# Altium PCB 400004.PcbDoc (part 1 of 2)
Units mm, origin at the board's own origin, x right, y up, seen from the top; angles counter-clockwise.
Board outline 80 x 40 mm, 4 copper layers (Top Layer, Mid-Layer 1, Mid-Layer 2, Bottom Layer), stack 1.582 mm thick; 116 components, 104 nets, 453 pads, 327 vias.
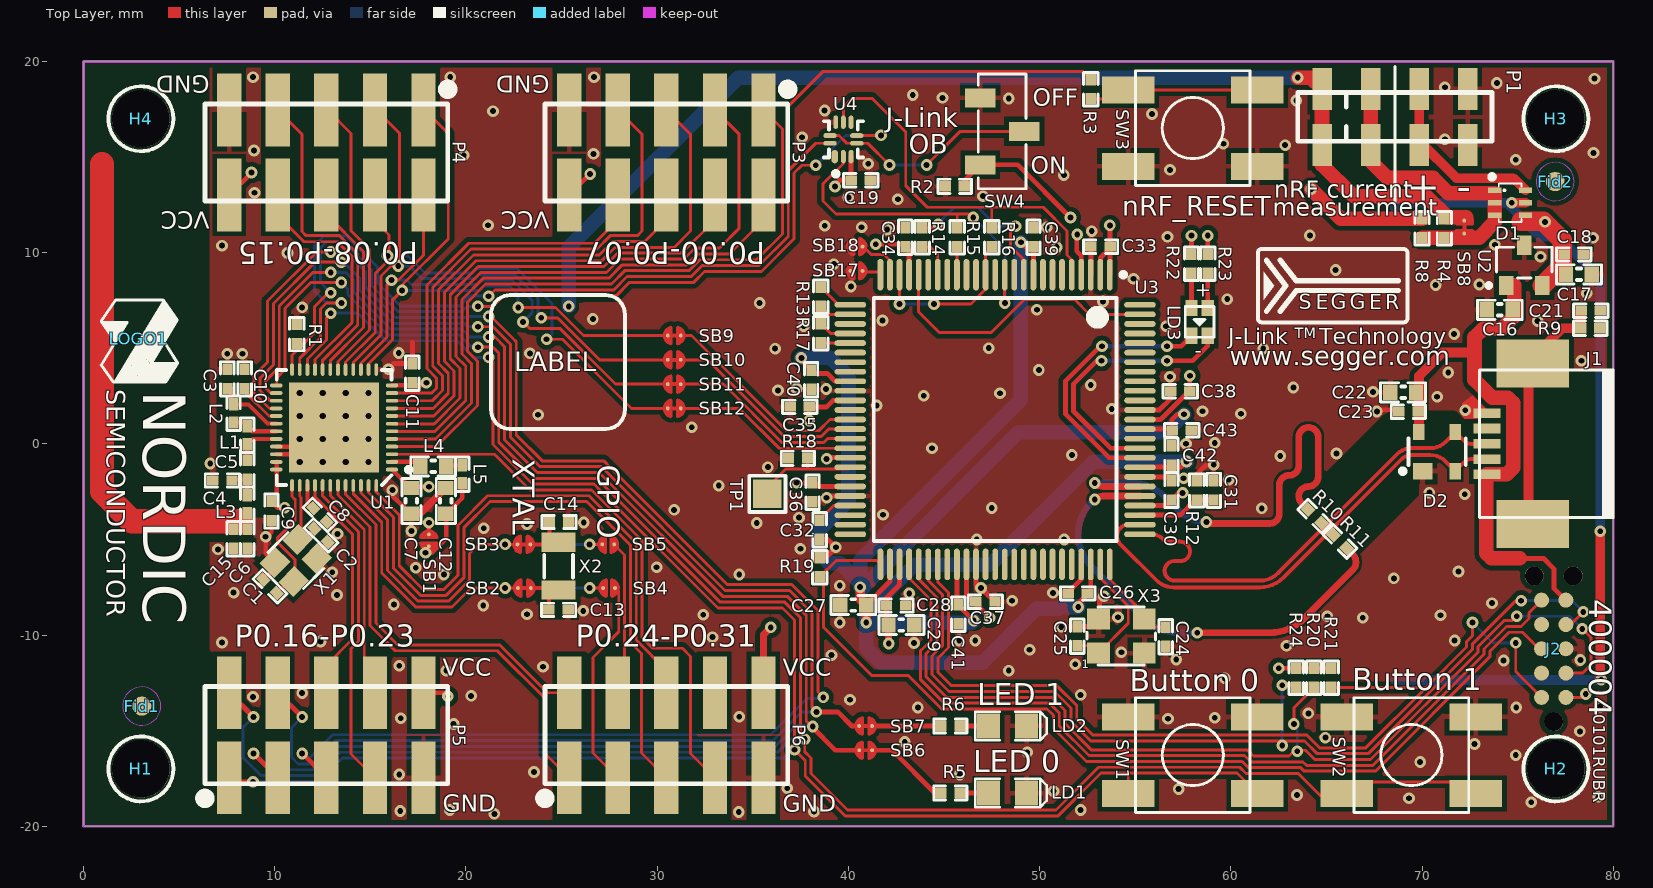
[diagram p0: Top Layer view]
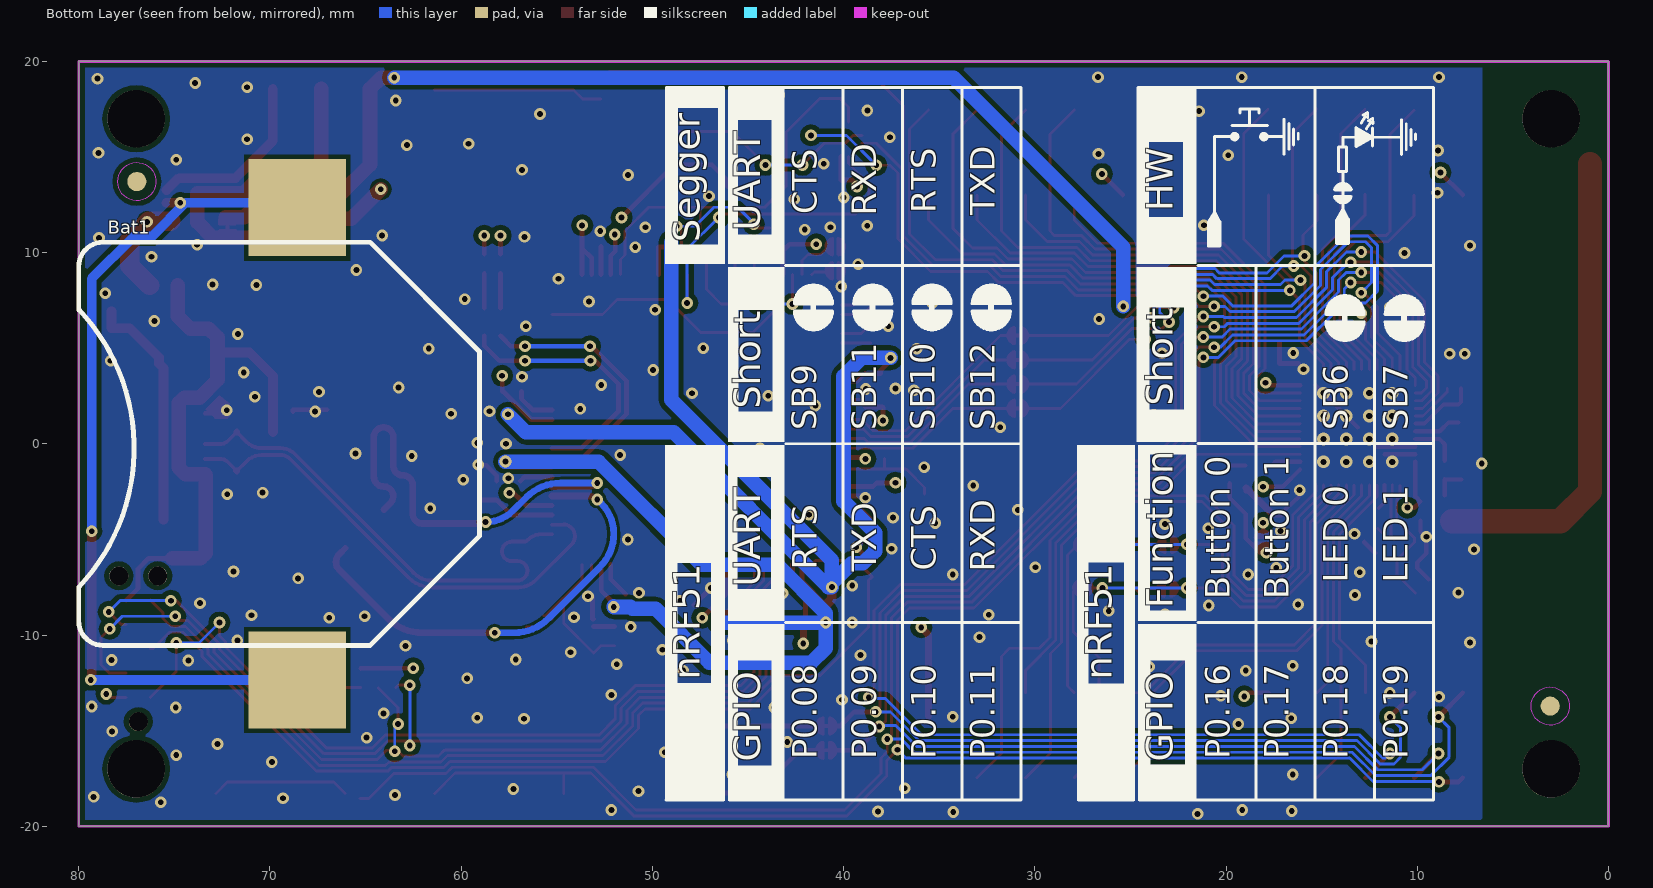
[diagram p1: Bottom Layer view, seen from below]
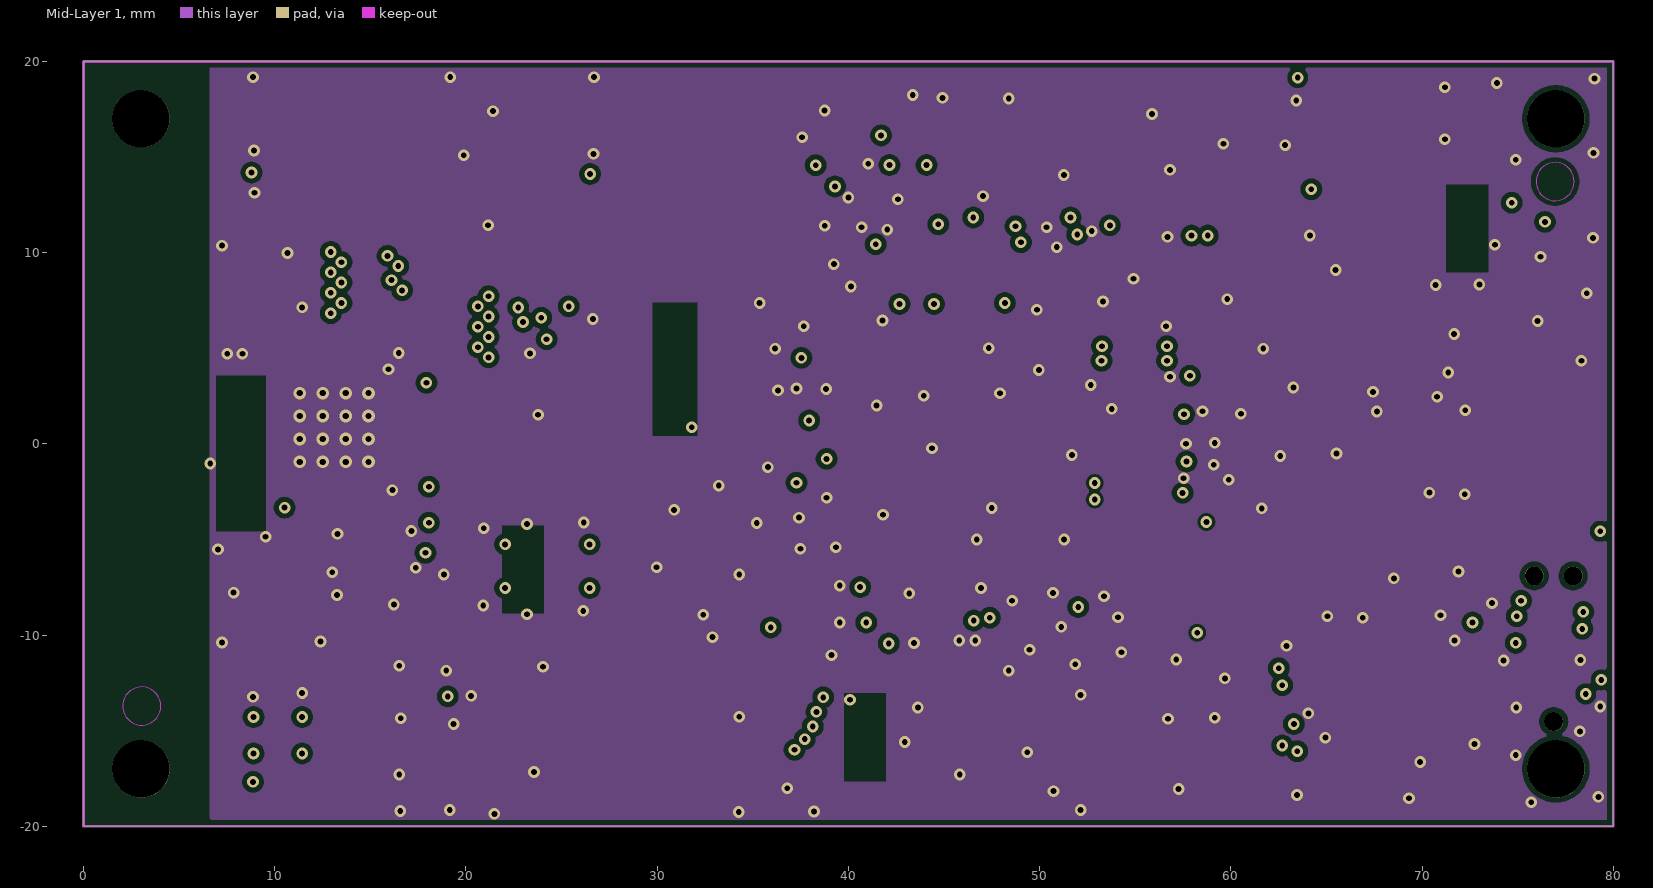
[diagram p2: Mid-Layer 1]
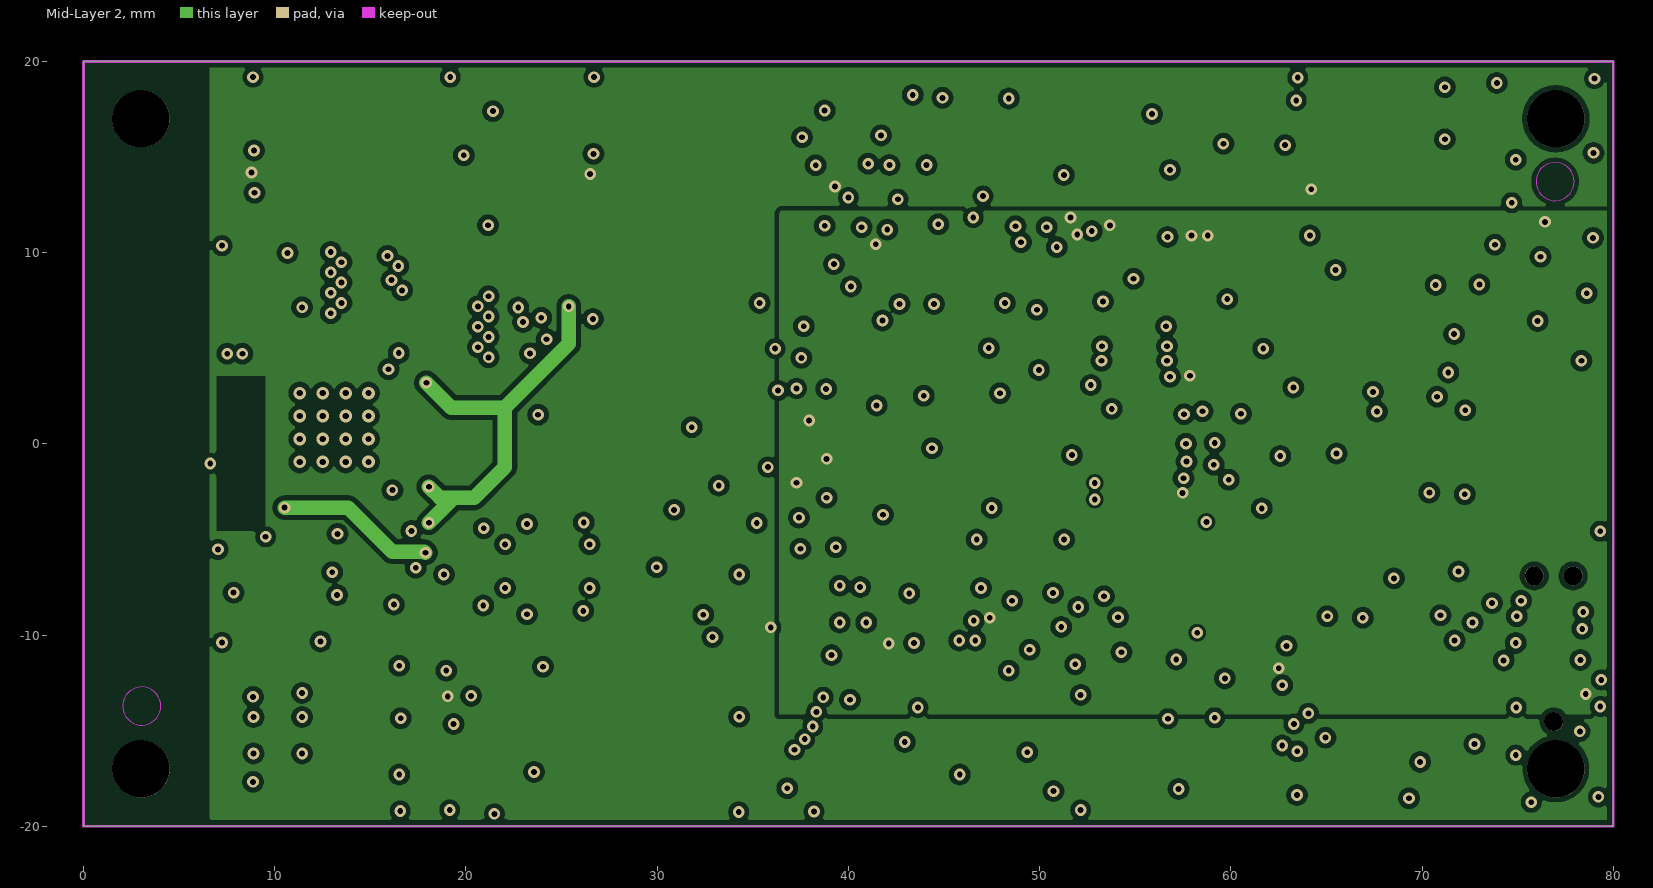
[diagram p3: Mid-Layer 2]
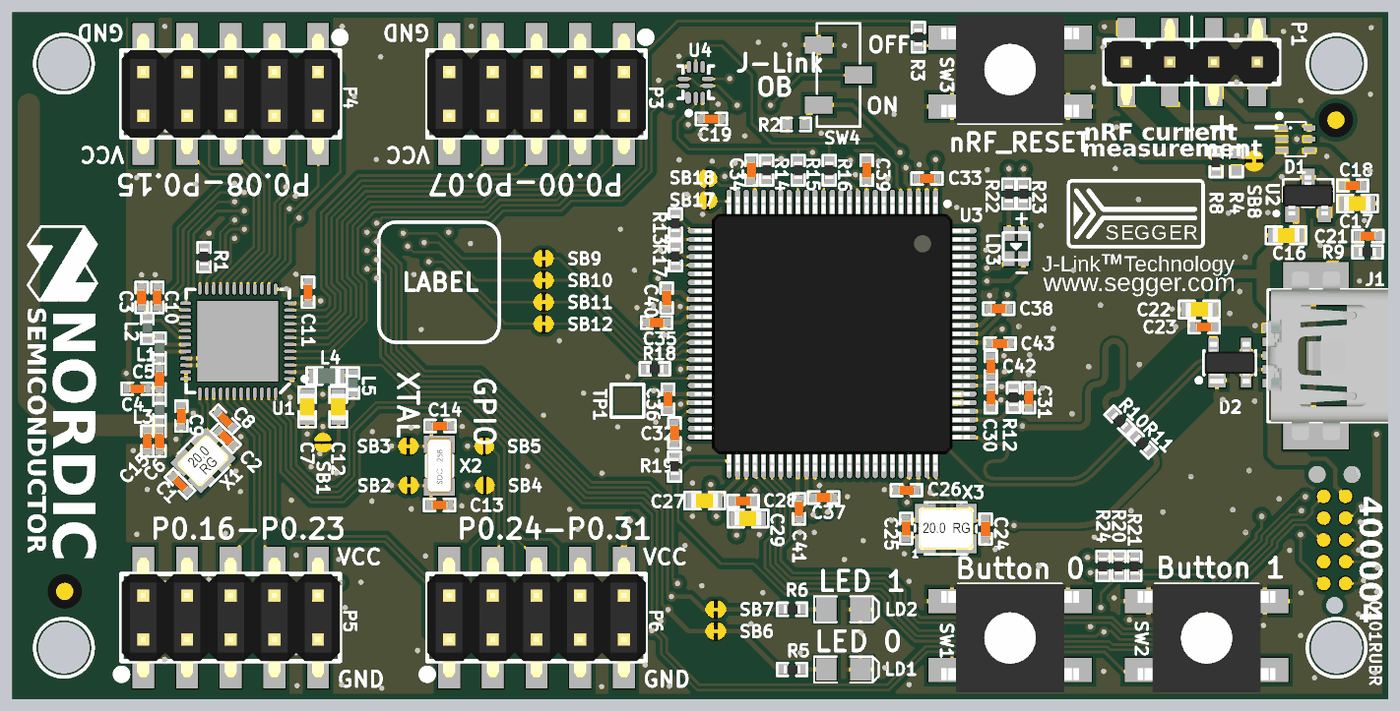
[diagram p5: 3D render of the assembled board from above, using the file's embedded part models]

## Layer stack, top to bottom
Top Layer: signal copper 0.0356
Dielectric: prepreg 0.18, FR-4, Dk 4.4
Mid-Layer 1: signal copper 0.0356
Dielectric: core 1.08, FR-4, Dk 4.4
Mid-Layer 2: signal copper 0.0356
Dielectric: prepreg 0.18, FR-4, Dk 4.4
Bottom Layer: signal copper 0.0356

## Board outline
0,-20 80,-20 80,20 0,20

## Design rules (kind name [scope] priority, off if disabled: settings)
Clearance USB_Poly_Clearance [(InNamedPolygon('Top_Layer-GND')) vs (OnLayer('Mechanical 3'))] p1: gap=0.254
Clearance USB_Clearance [(InDifferentialPairClass('All Differential Pairs'))] p2: gap=0.152
Clearance ANT_Clerance [InNet('ANT')] p3: gap=0.127
Clearance Polygon_Clearance [(InNamedPolygon('Top_Layer-GND')) or (InNamedPolygon('Bottom_Layer-GND')) or (InNamedPolygon('Mid_Layer_1-GND')) or (InNamedPolygon('Mid_Layer_2-VCC3')) or (InNamedPolygon('Mid_Layer_2-VCC_IO'))] p4: gap=0.254
Clearance SB_Clearance [HasFootprint('Solderbridge') or HasFootprint('QFN40P180X140X55-10N')] p5: gap=0.127
Clearance CSP_Clearance [HasFootprint('BGA4C40P2X2_76X76X62')] p6: gap=0.127
Clearance [All] p7: gap=0.152
ComponentClearance [All] p1 off: gap=0.254 collisioncheckmode=3 verticalgap=0.254 showdistances=FALSE
DiffPairsRouting [All] p1: maxlimit=0.254 minlimit=0.15 mostfreqgap=0.254 toplayer_maxgap=0.15 toplayer_prefgap=0.15 midlayer1_mingap=0.254 midlayer2_mingap=0.254 bottomlayer_maxgap=0.15 bottomlayer_prefgap=0.15 maxuncoupledlength=12.7
FabricationTestPointUsage TestPointUsage [All] p1: valid=0 allowmultiple=FALSE
FabricationTestpoint Testpoint [All] p1: side=3 testpointundercomponent=TRUE minsize=1.016 maxsize=2.54 preferedsize=1.524 minholesize=0 maxholesize=1.016 preferedholesize=0.813 testpointgrid=0.025 allowsidetop=TRUE allowsidebottom=TRUE usegrid=TRUE gridtolerance=0
Height [All] p1 off: minheight=0 maxheight=25.4 prefheight=12.7
HoleSize [All] p1: absolutevalues=TRUE maxlimit=5 minlimit=0.305 maxpercent=80.000 minpercent=20.000
MinimumAnnularRing [All] p1 off: minimumring=0.152
PolygonConnect PolygonConnect_1 [isVia and innet(gnd) or isVia and innet(VCC3) or isVia and innet(VCC_IO)] p1: connectstyle=Direct reliefconductorwidth=0.254 reliefentries=4 polygonreliefangle="90 Angle" airgapwidth=0.254
PolygonConnect [All] p2: connectstyle=Relief reliefconductorwidth=0.254 reliefentries=4 polygonreliefangle="90 Angle" airgapwidth=0.254
RoutingVias [All] p1: holewidth=0.305 width=0.61 viastyle="Through Hole" minholewidth=0.305 minwidth=0.61 maxholewidth=0.711 maxwidth=1.27
ShortCircuit ShortCircuit_1 [InNet('VCC_IO') vs InNet('NetSB8_2')] p1: allowed=TRUE
ShortCircuit ShortCircuit_2 [InNet('VCC_nRF') vs InNet('V3')] p2: allowed=TRUE
ShortCircuit [All] p3: allowed=FALSE
SilkToSolderMaskClearance SilkscreenOverComponentPads [IsPad] p1: minsilkscreentomaskgap=0.254 clearancetoexposedcopper=TRUE
SolderMaskExpansion [All] p1: expansion=0.076
Width Width_USB [(InDifferentialPairClass('All Differential Pairs'))] p1: maxlimit=0.35 minlimit=0.203 preferedwidth=0.35 midlayer1_minwidth=0.254 midlayer1_maxwidth=0.254 midlayer1_prefwidth=0.254 midlayer2_minwidth=0.254 midlayer2_maxwidth=0.254 midlayer2_prefwidth=0.254 bottomlayer_minwidth=0.35 minimp=50.000000 maximp=50.000000 favimp=50.000000
Width [All] p2: maxlimit=2.54 minlimit=0.152 preferedwidth=0.152
20 further rules are at their usual default settings.

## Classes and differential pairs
component class nrf51x22_ek_interfaces: Bat1 C16 C17 C18 C19 D1 Fid1 Fid2 H1 H2 H3 H4 LD1 LD2 LOGO1 P1 P3 P4 P5 P6 R2 R3 R4 R5 R6 R8 SB6 SB7 SB8 SB9 SB10 SB11 SB12 SW1 SW2 SW3 SW4 U2 U4
component class nRF51x22: C1 C2 C3 C4 C5 C6 C7 C8 C9 C10 C11 C12 C13 C14 C15 L1 L2 L3 L4 L5 R1 SB1 SB2 SB3 SB4 SB5 U1 X1 X2
component class l-link-ob-sam3u-lqfp: C21 C22 C23 C24 C25 C26 C27 C28 C29 C30 C31 C32 C33 C34 C35 C36 C37 C38 C39 C40 C41 C42 C43 D2 J1 J2 LD3 R9 R10 R11 R12 R13 R14 R15 R16 R17 R18 R19 R20 R21 R22 R23 R24 SB17 SB18 TP1 U3 X3
differential pair DFSD: +DFSD_P -DFSD_N
differential pair DHSD: +DHSD_P -DHSD_N

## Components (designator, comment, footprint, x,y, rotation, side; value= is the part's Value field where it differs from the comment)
Bat1 "Bat Holder CR2032" CR2032_HOLDER_SMD 68.572,-13.081 r90 bottom locked
C1 "12pF" CAPC1005X04L 9.754,-7.452 r135 top locked (schematic designator C7)
C2 "12pF" CAPC1005X04L 12.421,-4.785 r315 top locked
C3 "2.2nF" CAPC1005X04L 7.518,3.393 r90 top
C4 "0.8pF" CAPC1005X04L 7.264,-1.915 r180 top
C5 "2.2pF" CAPC1005X04L 8.56,-1.356 r270 top
C6 "1.5pF" CAPC1005X04L 8.56,-4.963 r270 top
C7 "4.7µF" CAPC1608X06L 17.145,-2.982 r270 top locked (schematic designator C9)
C8 "100nF" CAPC1005X04L 12.37,-3.719 r315 top locked (schematic designator C10)
C9 "1.0nF" CAPC1005X04L 9.83,-3.515 r270 top locked (schematic designator C8)
C10 "47nF" CAPC1005X04L 8.433,3.393 r90 top (schematic designator C11)
C11 "100nF" CAPC1005X04L 17.196,3.698 r90 top (schematic designator C12)
C12 "1.0µF" CAPC1608X06L 18.948,-2.982 r270 top locked (schematic designator C11)
C13 "12pF" CAPC1005X04L 24.841,-8.687 r0 top
C14 "12pF" CAPC1005X04L 24.867,-4.089 r0 top
C15 "1.2pF" CAPC1005X04L 7.849,-4.963 r270 top
C16 "1.0µF" CAPC1608X06L 74.066,7.01 r0 top
C17 "1.0µF" CAPC1608X06L 78.207,8.865 r180 top
C18 "100nF" CAPC1005X04L 77.927,9.906 r180 top
C19 "100nF" CAPC1005X04L 40.65,13.78 r180 top (schematic designator C20)
C21 "100nF" CAPC1005X04L 78.816,6.96 r180 top
C22 "10µF" CAPC1608X06L 69.012,2.692 r0 top
C23 "100nF" CAPC1005X04L 69.291,1.676 r0 top
C24 "18pF" CAPC1005X04L 56.591,-10.084 r270 top
C25 "18pF" CAPC1005X04L 51.968,-10.058 r90 top
C26 "100nF" CAPC1005X04L 51.994,-7.823 r180 top
C27 "10µF" CAPC1608X06L 40.259,-8.433 r0 top
C28 "100nF" CAPC1005X04L 42.494,-8.458 r180 top
C29 "10µF" CAPC1608X06L 42.774,-9.474 r180 top
C30 "100nF" CAPC1005X04L 56.896,-2.438 r270 top
C31 "10pF" CAPC1005X04L 59.106,-2.438 r270 top
C32 "10nF" CAPC1005X04L 38.506,-4.496 r90 top
C33 "100nF" CAPC1005X04L 53.188,10.312 r0 top
C34 "100nF" CAPC1005X04L 42.977,10.795 r270 top
C35 "100nF" CAPC1005X04L 37.465,1.93 r0 top
C36 "100nF" CAPC1005X04L 38.125,-2.54 r90 top
C37 "100nF" CAPC1005X04L 47.168,-8.255 r180 top
C38 "100nF" CAPC1005X04L 57.353,2.743 r0 top
C39 "100nF" CAPC1005X04L 49.682,10.795 r270 top
C40 "100nF" CAPC1005X04L 38.049,3.353 r90 top
C41 "100nF" CAPC1005X04L 45.745,-8.915 r90 top
C42 "100nF" CAPC1005X04L 56.896,-0.61 r270 top
C43 "100nF" CAPC1005X04L 57.429,0.711 r180 top
D1 "SD103ATW-7-F" SOT-363 73.812,13.259 r270 top
D2 "PRTR5V0U2X" SOT190P230X110-4L 70.79,-0.406 r90 top
Fid1 "Fiducial mark" Fiducial 3.048,-13.716 r0 top
Fid2 "Fiducial mark" Fiducial 76.962,13.716 r0 top
H1 "3mm,N.P" HOLE_NP_3MM 3,-17 r0 top locked
H2 "3mm,N.P" HOLE_NP_3MM 77,-17 r0 top locked
H3 "3mm,N.P" HOLE_NP_3MM 77,17 r0 top locked
H4 "3mm,N.P" HOLE_NP_3MM 3,17 r0 top locked
J1 "MiniUSB-B" UX60SC-MB-5ST 73.4,0 r180 top
J2 "TC2050-IDC" TC2050-IDC-NLFP 76.886,-10.719 r90 top locked
L1 "4.7nH" INDC1005X04L 8.56,0.447 r270 top
L2 "10nH" INDC1005X04L 7.849,1.59 r270 top
L3 "3.3nH" INDC1005X04L 8.56,-3.16 r270 top
L4 "10µH" INDC1608X06L 18.288,-1.179 r0 top locked (schematic designator L5)
L5 "15nH" INDC1005X04L 19.812,-1.585 r270 top locked (schematic designator L6)
LD1 "L0805G" LED_0805 49.327,-18.263 r180 top
LD2 "L0805G" LED_0805 49.327,-14.757 r180 top
LD3 "LTST-C195KGJRKT" LED_DUAL_0606 58.369,6.375 r0 top
LOGO1 "Nordic Logo M" NORDIC_LOGO_M 2.896,5.502 r270 top
P1 "Pin List 1x4" LIST_1x4_SMD 64.77,17.094 r0 top locked (schematic designator P2)
P3 "Pin Hdr 2x5" "Molex 15-91-2100" 30.48,15.24 r180 top
P4 "Pin Hdr 2x5" "Molex 15-91-2100" 12.7,15.24 r180 top locked
P5 "Pin Hdr 2x5" "Molex 15-91-2100" 12.7,-15.24 r0 top locked
P6 "Pin Hdr 2x5" "Molex 15-91-2100" 30.48,-15.24 r0 top locked
R1 "N.C." RESC1005X04L 11.151,5.74 r270 top
R2 "100k" RESC1005X04L 45.57,13.46 r0 top (schematic designator R5)
R3 "150R" RESC1005X04L 52.68,18.542 r90 top
R4 "N.C." RESC1005X04L 71.171,11.278 r270 top
R5 "220R" RESC1005X04L 45.339,-18.263 r180 top
R6 "220R" RESC1005X04L 45.339,-14.757 r180 top (schematic designator R2)
R8 "0R" RESC1005X04L 70.002,11.278 r90 top
R9 "10k" RESC1005X04L 78.791,6.045 r180 top
R10 "39R" RESC1005X04L 64.389,-3.785 r315 top
R11 "39R" RESC1005X04L 65.71,-5.105 r135 top
R12 "6k8" RESC1005X04L 58.217,-2.438 r270 top
R13 "0R" RESC1005X04L 38.557,7.696 r90 top
R14 "0R" RESC1005X04L 43.866,10.795 r90 top
R15 "150R" RESC1005X04L 45.695,10.795 r90 top
R16 "150R" RESC1005X04L 47.498,10.795 r90 top
R17 "0R" RESC1005X04L 38.557,5.791 r90 top
R18 "1k" RESC1005X04L 37.363,-0.762 r0 top
R19 "4k7" RESC1005X04L 38.506,-6.452 r90 top
R20 "4k7" RESC1005X04L 64.338,-12.243 r90 top
R21 "4k7" RESC1005X04L 65.253,-12.243 r90 top
R22 "220R" RESC1005X04L 57.944,9.423 r90 top
R23 "220R" RESC1005X04L 58.794,9.423 r90 top
R24 "4k7" RESC1005X04L 63.424,-12.243 r90 top
SB1 "Solderbridge" Solderbridge 18.059,-4.735 r270 top
SB2 "Solderbridge" Solderbridge_Shorted#1 23.393,-7.544 r180 top net-tie
SB3 "Solderbridge" Solderbridge_Shorted#1 23.368,-5.258 r180 top net-tie
SB4 "Solderbridge" Solderbridge 27.17,-7.544 r0 top
SB5 "Solderbridge" Solderbridge 27.127,-5.258 r0 top
SB6 "Solderbridge" Solderbridge_Shorted#1 40.564,-16.027 r0 top net-tie
SB7 "Solderbridge" Solderbridge_Shorted#1 40.564,-14.757 r0 top net-tie
SB8 "Solderbridge" Solderbridge_Shorted#2 72.212,10.998 r90 top net-tie
SB9 "Solderbridge" Solderbridge_Shorted#1 31.233,5.662 r180 top net-tie (schematic designator SB12)
SB10 "Solderbridge" Solderbridge_Shorted#1 31.233,4.392 r180 top net-tie (schematic designator SB13)
SB11 "Solderbridge" Solderbridge_Shorted#1 31.233,3.122 r180 top net-tie (schematic designator SB14)
SB12 "Solderbridge" Solderbridge_Shorted#1 31.233,1.852 r180 top net-tie (schematic designator SB15)
SB17 "Solderbridge" Solderbridge 40.742,9.042 r180 top
SB18 "Solderbridge" Solderbridge 40.742,10.312 r180 top
SW1 "PB SW" ALPS_SKHUxxx010_WO_GND 58.014,-16.281 r180 top
SW2 "PB SW" ALPS_SKHUxxx010_WO_GND 69.444,-16.281 r180 top
SW3 "PB SW" ALPS_SKHUxxx010_WO_GND 58.014,16.51 r0 top
SW4 "Switch" CJS-120xA 48.043,16.341 r270 top
TP1 "1.5mm,SMD" TP_SMD_1.5mmX1.5mm 35.763,-2.616 r0 top
U1 "nRF51822-QFAA" QFN40P600X600X90-48N 13.106,0.853 r180 top locked
U2 "AP7333-33SAG-7" SOT-23A 74.397,8.28 r0 top
U3 "ATSAM3U2CA-AU" TSQFP50P1600X1600X160-100N 47.676,1.27 r270 top locked
U4 "STG3684A" QFN40P180X140X55-10N 39.74,15.92 r90 top (schematic designator U5)
X1 "16MHz" BT-XTAL_2520 11.1,-6.106 r45 top locked
X2 "32.768kHz" FC-135 24.841,-6.401 r90 top
X3 "12MHz" BT-XTAL_3225 54.28,-10.058 r0 top

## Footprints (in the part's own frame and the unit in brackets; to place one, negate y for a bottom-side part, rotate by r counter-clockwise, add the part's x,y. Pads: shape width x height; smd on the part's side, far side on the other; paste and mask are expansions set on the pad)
ALPS_SKHUxxx010_WO_GND [mm] "6.2×6.5mm TACT Switch, without ground connector"
  rect 2.75x1.4 smd: 1(-3.375,2) 1(3.375,2) 2(-3.375,-2) 2(3.375,-2)
  silkscreen extent -3,-3 3,3, body extent -4,-3 4,3.3, height 3.1
BT-XTAL_2520 [mm] "TSX-2520"
  rect 1.2x1.1 smd: 1(-0.85,-0.7) 2(0.85,-0.7) 3(0.85,0.7) 4(-0.85,0.7)
  silkscreen extent -1.55,-1.33 1.53,1.32, body extent -1.25,-1 1.27,1, height 0.56
BT-XTAL_3225 [mm] "Mercury X32 series"
  rect 1.2x1.1 smd: 1(-1.194,-0.89) 2(1.194,-0.891) 3(1.194,0.888) 4(-1.194,0.891)
  silkscreen extent -1.8,-1.5 1.78,1.52, body extent -1.6,-1.25 1.61,1.25, height 0.81
CAPC1005X04L [mm] "Chip Capacitor, 2-Leads, Body 1.0x0.5mm, IPC High Density"
  rect 0.6x0.5 smd: 1(-0.5,0) 2(0.5,0)
  silkscreen extent -0.9,-0.35 0.9,0.35, body extent -0.51,-0.25 0.51,0.25, height 0.5
CAPC1608X06L [mm] "Chip Capacitor, 2-Leads, Body 1.6x0.8mm, IPC High Density"
  rect 0.75x0.8 smd: 1(-0.675,0) 2(0.675,0)
  silkscreen extent -1.17,-0.5 1.17,0.5, body extent -0.8,-0.43 0.8,0.43, height 0.8
CJS-120xA [mm] "Slide Switches - SPDT, SMD, ON-ON"
  rect 1x1.6 smd: 1(1.75,-1.15) 2(0,1.15) 3(-1.75,-1.15)
  silkscreen extent -3,-1.25 3,1.25, body extent -3,-1.39 3,1.39, height 2.5
CR2032_HOLDER_SMD [mm] "CR2032 - SMD mount coin cell bat holder"
  rect 5.08x5.08 smd: 1(0.731,0) 1(25.431,0)
  round 18 on Bottom Solder paste+0: 2(13.081,0)
  silkscreen extent 2.54,-9.53 23.62,11.43, body extent -2.29,-10.27 28.45,9.78, height 3.96
FC-135 [mm] "EPSON TOYOCOM - FC-135 32.768KHZ ±20PPM,9.0PF - CRYSTAL, SM, WATCH"
  rect 1x1.8 smd: 1(-1.25,0) 2(1.25,0)
  silkscreen extent -0.6,-0.75 0.6,0.75, body extent -1.6,-0.75 1.6,0.75, height 0.81
Fiducial [mm] "Fiducial Mark"
  round 1 smd paste-10 mask+0.5: 0(0,0)
  round 1 smd far side paste-10 mask+0.5: 0(0,0)
  Keep-Out Layer circle w0.01: c0,0 r1
HOLE_NP_3MM [mm] "Regular 3mm non-plated hole"
  round 3 hole 3 unplated paste+0 mask+0: ""(0,0)
  silkscreen extent -1.7,-1.7 1.7,1.7
INDC1005X04L [mm] "Chip Inductor, 2-Leads, Body 1.0x0.5mm, IPC High Density"
  rect 0.65x0.5 smd: 1(-0.475,0) 2(0.475,0)
  silkscreen extent -0.9,-0.35 0.9,0.35, body extent -0.5,-0.3 0.5,0.3, height 0.5
INDC1608X06L [mm] "Chip Inductor, 2-Leads, Body 1.6x0.8mm, IPC High Density"
  rect 0.75x0.8 smd: 1(-0.675,0) 2(0.675,0)
  silkscreen extent -1.17,-0.5 1.17,0.5, body extent -0.8,-0.48 0.8,0.48, height 0.8
LED_0805 [mm]
  rect 1.2x1.3 smd: 1(0,0) 2(2,0)
  silkscreen extent -1.05,-0.75 2.7,0.75
LED_DUAL_0606 [mm]
  rect 0.65x0.85 smd paste+0: 1(0.425,0.725) 2(-0.425,0.725) 3(0.425,-0.725) 4(-0.425,-0.725)
  silkscreen extent -0.75,-0.8 0.75,0.8
LIST_1x4_SMD [mm] "Pin List, 2.54mm, SMD"
  rect 1.02x2.19 smd: 1(0,-1.465) 1(0,1.465) 2(2.54,-1.465) 2(2.54,1.465) 3(5.08,-1.465) 3(5.08,1.465) 4(7.62,-1.465) 4(7.62,1.465)
  silkscreen extent -1.27,-1.27 8.89,1.27, body extent -1.27,-2.5 8.89,2.5, height 9.82
"Molex 15-91-2100" [mil] "MOLEX - 15-91-2100 - BOARD-BOARD CONN, HEADER, 10WAY, 2ROW"
  rect 50x150 smd: 1(-200,-87.5) 2(-200,87.5) 3(-100,-87.5) 4(-100,87.5) 5(0,-87.5) 6(0,87.5) 7(100,-87.5) 8(100,87.5) 9(200,-87.5) 10(200,87.5)
  silkscreen extent -260,-140 250,100, body extent -250,-138 250,138, height 380
NORDIC_LOGO_M [mm] "Medium Nordic Logo"
  silkscreen extent -2.03,-1.98 2.28,2.02
QFN40P180X140X55-10N [mm] "QFN, 10-Leads, Body 1.5x1.9mm (max), Pitch 0.40mm, IPC Medium Density"
  oval 0.7x0.35 smd: 1(-0.9,0.45)
  oval 0.7x0.25 smd: 2(-0.9,0) 3(-0.9,-0.4) 6(0.9,-0.4) 7(0.9,0) 8(0.9,0.4)
  oval 0.25x0.7 smd: 4(-0.2,-0.7) 5(0.2,-0.7) 9(0.2,0.7) 10(-0.2,0.7)
  silkscreen extent -1.92,-1.02 0.95,1.03, body extent -0.95,-0.75 0.95,0.75, height 0.55
QFN40P600X600X90-48N [mm] "QFN, 48-Leads, Body 6,0x6,0mm (max), Pitch 0,40mm, IPC Medium Density"
  oval 0.65x0.2 smd: 1(-3.025,2.2) 2(-3.025,1.8) 3(-3.025,1.4) 4(-3.025,1) 5(-3.025,0.6) 6(-3.025,0.2) 7(-3.025,-0.2) 8(-3.025,-0.6) 9(-3.025,-1) 10(-3.025,-1.4) 11(-3.025,-1.8) 12(-3.025,-2.2) 25(3.025,-2.2) 26(3.025,-1.8) 27(3.025,-1.4) 28(3.025,-1) 29(3.025,-0.6) 30(3.025,-0.2) 31(3.025,0.2) 32(3.025,0.6) 33(3.025,1) 34(3.025,1.4) 35(3.025,1.8) 36(3.025,2.2)
  oval 0.2x0.65 smd: 13(-2.2,-3.025) 14(-1.8,-3.025) 15(-1.4,-3.025) 16(-1,-3.025) 17(-0.6,-3.025) 18(-0.2,-3.025) 19(0.2,-3.025) 20(0.6,-3.025) 21(1,-3.025) 22(1.4,-3.025) 23(1.8,-3.025) 24(2.2,-3.025) 37(2.2,3.025) 38(1.8,3.025) 39(1.4,3.025) 40(1,3.025) 41(0.6,3.025) 42(0.2,3.025) 43(-0.2,3.025) 44(-0.6,3.025) 45(-1,3.025) 46(-1.4,3.025) 47(-1.8,3.025) 48(-2.2,3.025)
  rect 4.7x4.7 smd: 49(0,0)
  silkscreen extent -4.03,-3 3,3, body extent -3,-3 3,3, height 0.9
RESC1005X04L [mm] "Chip Resistor, 2-Leads, Body 1.0x0.5mm, IPC High Density"
  rect 0.6x0.55 smd: 1(-0.5,0) 2(0.5,0)
  silkscreen extent -0.87,-0.38 0.88,0.38, body extent -0.5,-0.25 0.5,0.25, height 0.3
Solderbridge [mm]
  round 0.2 smd paste-10: 1(0,0) 2(0.625,0)
  Top Layer region: 0.389,0.432 0.465,0.505 0.583,0.467 0.648,0.424 0.721,0.351 0.775,0.292 0.833,0.193 0.861,0.099 0.856,-0.122 0.831,-0.193 0.747,-0.33 0.663,-0.411 0.571,-0.469 0.47,-0.5 0.419,-0.483 0.389,-0.43
  Top Layer region: 0.236,-0.432 0.16,-0.505 0.042,-0.467 -0.023,-0.424 -0.097,-0.351 -0.15,-0.292 -0.208,-0.193 -0.236,-0.099 -0.231,0.122 -0.206,0.193 -0.122,0.33 -0.038,0.411 0.054,0.469 0.155,0.5 0.206,0.483 0.236,0.43
  Top Layer lines w0.152: 0.465,-0.431 ccw(c0.355,0) 0.465,0.431 ; 0.159,-0.431 cw(c0.27,0) 0.159,0.431
Solderbridge_Shorted#1 [mm]
  round 0.2 smd paste-10: 1(0,0) 2(0.676,0)
  Top Layer region: 0.44,0.432 0.516,0.505 0.634,0.467 0.698,0.424 0.772,0.351 0.826,0.292 0.884,0.193 0.912,0.099 0.907,-0.122 0.881,-0.193 0.798,-0.33 0.714,-0.411 0.622,-0.469 0.521,-0.5 0.47,-0.483 0.44,-0.43
  Top Layer region: 0.236,-0.432 0.16,-0.505 0.042,-0.467 -0.023,-0.424 -0.097,-0.351 -0.15,-0.292 -0.208,-0.193 -0.236,-0.099 -0.231,0.122 -0.206,0.193 -0.122,0.33 -0.038,0.411 0.054,0.469 0.155,0.5 0.206,0.483 0.236,0.43
  Top Layer lines w0.152: 0.516,0.431 cw(c0.406,0) 0.516,-0.431 ; 0.159,0.431 ccw(c0.27,0) 0.159,-0.431
  Top Layer lines w0.203: 0.676,0 0,0
Solderbridge_Shorted#2 [mm]
  round 0.2 smd paste-10: 1(0,0) 2(0.676,0)
  Top Layer region: 0.44,0.432 0.516,0.505 0.634,0.467 0.699,0.424 0.772,0.351 0.826,0.292 0.884,0.193 0.912,0.099 0.907,-0.122 0.881,-0.193 0.798,-0.33 0.714,-0.411 0.622,-0.469 0.521,-0.5 0.47,-0.483 0.44,-0.43
  Top Layer region: 0.236,-0.432 0.16,-0.505 0.042,-0.467 -0.023,-0.424 -0.097,-0.351 -0.15,-0.292 -0.208,-0.193 -0.236,-0.099 -0.231,0.122 -0.206,0.193 -0.122,0.33 -0.038,0.411 0.054,0.469 0.155,0.5 0.206,0.483 0.236,0.43
  Top Layer lines w0.152: 0.159,0.431 ccw(c0.27,0) 0.159,-0.431 ; 0.516,0.431 cw(c0.406,0) 0.779,0.241 cw(c0.406,0) 0.843,0.077 cw(c0.406,0) 0.843,-0.077 cw(c0.406,0) 0.838,-0.102 cw(c0.406,0) 0.516,-0.431
  Top Layer lines w0.203: 0,0 0.676,0
SOT190P230X110-4L [mm] "SOT143, 4-Leads, Body 3.0x2.5mm (max), Pitch 1.90mm, IPC High Density"
  rect 0.85x1 smd: 1(-1.025,0.75)
  rect 0.85x0.6 smd: 2(-1.025,-0.95) 3(1.025,-0.95) 4(1.025,0.95)
  silkscreen extent -1.15,-1.5 0.7,1.92, body extent -1.21,-1.46 1.21,1.46, height 1
SOT-23A [mil] "SOT-23 footprint"
  rect 30x40 smd: 1(0,0) 2(74.8,0) 3(37.4,82.68)
  silkscreen extent -39,-4 94,79, body extent -20,-5 95,87, height 39
SOT-363 [mm] "SOT-363 (SC88)"
  rect 0.3x0.7 smd: 1(0,0) 2(0.65,0) 3(1.3,0) 4(1.3,1.6) 5(0.65,1.6) 6(0,1.6)
  silkscreen extent -0.82,-0.27 1.65,1.4, body extent -0.45,0.13 1.75,1.48, height 1.1
TC2050-IDC-NLFP [mil]
  round 39 hole 39 unplated: 0(-150,0) 0(150,-40) 0(150,40)
  round 31 smd paste-196.85: 1(-100,-25) 2(-50,-25) 3(0,-25) 4(50,-25) 5(100,-25) 6(100,25) 7(50,25) 8(0,25) 9(-50,25) 10(-100,25)
  Top Layer pour cut-out: -100,25 -100,-25 100,-25 100,25
TP_SMD_1.5mmX1.5mm [mm]
  rect 1.5x1.5 smd paste-5: 1(0,0)
  silkscreen extent -0.95,-0.95 0.95,0.95
TSQFP50P1600X1600X160-100N [mm] "TSQFP, 100-Leads, Body 16,0x16,0mm (max), Pitch 0,50mm, IPC Medium Density"
  oval 1.65x0.3 smd: 1(-7.575,6) 2(-7.575,5.5) 3(-7.575,5) 4(-7.575,4.5) 5(-7.575,4) 6(-7.575,3.5) 7(-7.575,3) 8(-7.575,2.5) 9(-7.575,2) 10(-7.575,1.5) 11(-7.575,1) 12(-7.575,0.5) 13(-7.575,0) 14(-7.575,-0.5) 15(-7.575,-1) 16(-7.575,-1.5) 17(-7.575,-2) 18(-7.575,-2.5) 19(-7.575,-3) 20(-7.575,-3.5) 21(-7.575,-4) 22(-7.575,-4.5) 23(-7.575,-5) 24(-7.575,-5.5) 25(-7.575,-6) 51(7.575,-6) 52(7.575,-5.5) 53(7.575,-5) 54(7.575,-4.5) 55(7.575,-4) 56(7.575,-3.5) 57(7.575,-3) 58(7.575,-2.5) 59(7.575,-2) 60(7.575,-1.5) 61(7.575,-1) 62(7.575,-0.5) 63(7.575,0) 64(7.575,0.5) 65(7.575,1) 66(7.575,1.5) 67(7.575,2) 68(7.575,2.5) 69(7.575,3) 70(7.575,3.5) 71(7.575,4) 72(7.575,4.5) 73(7.575,5) 74(7.575,5.5) 75(7.575,6)
  oval 0.3x1.65 smd: 26(-6,-7.575) 27(-5.5,-7.575) 28(-5,-7.575) 29(-4.5,-7.575) 30(-4,-7.575) 31(-3.5,-7.575) 32(-3,-7.575) 33(-2.5,-7.575) 34(-2,-7.575) 35(-1.5,-7.575) 36(-1,-7.575) 37(-0.5,-7.575) 38(0,-7.575) 39(0.5,-7.575) 40(1,-7.575) 41(1.5,-7.575) 42(2,-7.575) 43(2.5,-7.575) 44(3,-7.575) 45(3.5,-7.575) 46(4,-7.575) 47(4.5,-7.575) 48(5,-7.575) 49(5.5,-7.575) 50(6,-7.575) 76(6,7.575) 77(5.5,7.575) 78(5,7.575) 79(4.5,7.575) 80(4,7.575) 81(3.5,7.575) 82(3,7.575) 83(2.5,7.575) 84(2,7.575) 85(1.5,7.575) 86(1,7.575) 87(0.5,7.575) 88(0,7.575) 89(-0.5,7.575) 90(-1,7.575) 91(-1.5,7.575) 92(-2,7.575) 93(-2.5,7.575) 94(-3,7.575) 95(-3.5,7.575) 96(-4,7.575) 97(-4.5,7.575) 98(-5,7.575) 99(-5.5,7.575) 100(-6,7.575)
  silkscreen extent -7.7,-6.35 6.35,6.83, body extent -8,-8 8,8, height 1.6
UX60SC-MB-5ST [mm] "Mini USB B/AB female"
  rect 1.4x0.5 smd: 1(0,1.6) 2(0,0.8) 3(0,0) 4(0,-0.8) 5(0,-1.6)
  rect 3.8x2.5 smd: 6(-2.4,4.2) 6(-2.4,-4.2)
  Top Layer pour cut-out: -6.6,3.85 -6.6,-3.85 -4,-3.85 -4,-1.5 -2.5,-1.5 -2.5,1.5 -4,1.5 -4,3.85
  silkscreen extent -6.6,-3.85 0.4,3.85, body extent -6.6,-4.9 0.4,4.9, height 3.95

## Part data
Bat1: library part "Bat Holder CR2032 SMD", "Bat Holder CR2032 SMD"
C1 C2 C13 C14: library part C0402-12p, "Capacitor, NP0, ±2%"
C3: library part C0402-2n2, "Capacitor, X7R, ±10%"
C4: library part C0402-0.8p, "Capacitor, NP0, ±5%"
C5: library part C0402-2.2p, "Capacitor, NP0, ±0.1pF"
C6: library part C0402-1.5p, "Capacitor, NP0, ±0.1pF"
C7: library part C0603-4µ7, "Capacitor, X5R, ±10%"
C8 C11 C18 C19 C21 C23 C26 C28 C30 C33 C34 C35 C36 C37 C38 C39 C40 C41 C42 C43: library part C0402-100n, "Capacitor, X7R, ±10%"
C9: library part C0402-1n0, "Capacitor, X7R, ±10%"
C10: library part C0402-47n, "Capacitor, X7R, ±10%"
C12: library part C0603-1µ0, "Capacitor, X7R, ±10%"
C15: library part C0402-1.2p, "Capacitor, NP0, ±0.1pF"
C16 C17: library part C0603-1µ0, "Capacitor, X5R, ±10%"
C22 C27 C29: library part C0603-10µ, "Capacitor, X5R, ±10%"
C24 C25: library part C0402-18p, "Capacitor, NP0, ±5%"
C31: library part C0402-10p, "Capacitor, NP0, ±2%"
C32: library part C0402-10n, "Capacitor, X7R, ±10%"
D1: "Surface Mount Schottky Barrier Diode Array"
D2: "Ultra low capacitance double rail-to-rail ESD protection diode"
Fid1 Fid2: library part Fid-Mark, "Fiducial Mark"
H1 H2 H3 H4: library part Hole_3MM_NP, "Regular Non-Plated, 3mm hole"
J1: library part "Hirose UX60SC-MB-5ST", "Hirose MiniUSB-B-SMT"
J2: library part TC2050-IDC-NLFP, "CBL PLUG-OF-NAILS 10-PIN"
L1: library part L0402-4n7, "Inductor, 160mA, ±0.1nH"
L2: library part L0402-10n, "Inductor, 100mA, ±2%"
L3: library part L0402-3n3, "Inductor, 190mA, ±0.1nH"
L4: library part L0603-10µ, "Inductor, 80mA, ±10%"
L5: library part L0402-15n, "Inductor, 320mA, ±5%"
LD1 LD2: library part SML-210PT, "LED, SMD, 0805, GREEN"
LD3: "Avago, HSMF-A203 Bi-Color LED"
LOGO1: "Nordic Logo, medium size"
P1: library part "Pin List 1x4 SMD", "Pin List 1x4, 2.54mm (100mil)"
P3 P4 P5 P6: library part "Pin Header 2x5 SMD", "Pin Header 2x5, 2.54mm (100mil) SMD"
R1 R4: library part R0402-N.C., "Not mounted"
R2: library part R0402-100k, "Resistor, ±1%, 0.063W"
R3 R15 R16: library part R0402-150, "Resistor, ±1%, 0.063W"
R5 R6 R22 R23: library part R0402-220, "Resistor, ±1%, 0.063W"
R8 R13 R14 R17: library part R0402-0R, "Resistor, ±5%, 0.063W"
R9: library part R0402-10k, "Resistor, ±1%, 0.063W"
R10 R11: library part R0402-39R, "Resistor, ±1%, 0.063W"
R12: library part R0402-6k8, "Resistor, ±1%, 0.063W"
R18: library part R0402-1k0, "Resistor, ±1%, 0.063W"
R19 R20 R21 R24: library part R0402-4k7, "Resistor, ±1%, 0.063W"
SB2 SB3 SB6 SB7 SB8 SB9 SB10 SB11 SB12: library part "Solderbridge Shorted", "Shorted Solderbridge"
SW1 SW2 SW3: library part ALPS_SKHUALE010, "ALPS - SKHUALE010 - TACTILE SWITCH, SPNO, SMD, 6.5x6.2x2.5mm"
SW4: library part CJS-1200TA, "SMD slide Switch (ON-ON)"
TP1: library part TP_SMD_1.5MM, "Regular Plated, 1.5mm hole"
U1: library part nRF51822-QFAA-XLR2.4, "Multi-protocol Bluetooth Low Energy and 2.4GHz proprietary system-on-chip"
U2: "300mA, Low Quiescent Current, Fast Transient Low Dropout Linear Regulator"
U3: "IC MCU 32bit 128kB flash 100LQFP"
U4: library part STG3684AU, "Low voltage 0.5 ohm max dual SPDT switch with break-before-make"
X1: library part NX2520SA-16MHZ-STD-CSW-5, "XTAL SMD 2520, 16MHz, 8pF, ±15ppm"
X2: library part "XTAL_FC-135 32.768k", "EPSON TOYOCOM - FC-135 32.768KHZ ±20PPM,9.0PF - CRYSTAL, SM, WATCH"
X3: library part "XTAL SMD 12MHz (3225)", "XTAL SMD 3225, 12MHz, 18pF, ±30ppm"

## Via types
v1: diameter 0.61, hole 0.305, Top Layer to Bottom Layer, tented both sides, 311 vias
v2: diameter 0.66, hole 0.33, Top Layer to Bottom Layer, tented both sides, 16 vias

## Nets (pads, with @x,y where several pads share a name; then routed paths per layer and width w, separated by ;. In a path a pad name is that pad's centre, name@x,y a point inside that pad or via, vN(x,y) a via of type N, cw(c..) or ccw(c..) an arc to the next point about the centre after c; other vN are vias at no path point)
ANT: C6.1 C15.1 L3.2 | length 25
  Top Layer w1.27: 0.965,14.629 0.965,-2.489 2.525,-4.049 8.179,-4.049
ANT1: L1.1 L2.2 U1.31 | length 2.4
  Top Layer w0.229: L2.2@7.849,1.115 8.367,1.115 8.828,0.653 U1.31@10.106,0.653
ANT2: C5.1 L1.2 U1.32 | length 2.5
  Top Layer w0.229: C5.1@8.56,-0.881 L1.2@8.56,-0.028 8.841,0.253 U1.32@10.106,0.253
AVDD: C9.1 C12.2 L5.2 SB1.2 U1.35 U1.36 | length 16
  Top Layer w0.229: U1.35@10.106,-0.947 10.106,-2.739 C9.1@9.83,-3.015 10.152,-3.338 v1(10.516,-3.338) ; v1(17.882,-5.7) 18.212,-5.7 18.974,-4.938 18.974,-3.668 19.812,-2.83 L5.2@19.812,-2.06
  Mid-Layer 2 w0.762: v1(10.516,-3.338) 13.853,-3.338 16.154,-5.639 17.821,-5.639 v1(17.882,-5.7)
BUTTON0: P5.1 SW1.1 U1.22 | length 102.2
  Top Layer w0.152: U1.22@11.706,3.878 11.706,4.442 12.7,5.436 12.7,6.604 v1(12.929,6.833) ; 21.412,4.293 21.412,-0.039 23.481,-2.108 26.694,-2.108 27.072,-2.486 27.076,-2.486 33.175,-8.585 36.551,-8.585 37.186,-9.219 v1(37.186,-16.002) 37.744,-16.561 37.744,-17.373 39.828,-19.456 50.978,-19.456 53.213,-17.221 60.328,-17.221 SW1.1@61.389,-18.281 ; SW1.1@54.639,-18.281 54.639,-17.224
  Top Layer w0.254: P5.1@7.62,-17.462 7.836,-17.678 v1(8.865,-17.678)
  Bottom Layer w0.152: v1(8.865,-17.678) 8.89,-17.653 12.316,-17.653 13.535,-16.434 36.754,-16.434 v1(37.186,-16.002) ; v1(12.929,6.833) 14.357,6.833 15.801,5.389 19.536,5.389 20.404,4.521 v1(21.184,4.521)
BUTTON1: P5.2 SW2.1 U1.25 | length 121.8
  Top Layer w0.152: U1.25@10.106,3.053 10.106,3.45 10.541,3.884 10.541,7.087 11.887,8.433 v1(13.487,8.433) ; v1(20.625,5.055) 21.407,5.055 21.717,4.745 21.717,4.3 21.717,0.087 23.607,-1.803 26.82,-1.803 27.1,-2.083 27.104,-2.083 33.302,-8.28 36.678,-8.28 37.49,-9.093 37.49,-15.215 v1(37.719,-15.443) 37.719,-16.104 38.049,-16.435 38.049,-17.247 39.954,-19.152 50.852,-19.152 53.087,-16.916 60.469,-16.916 60.8,-17.247 63.525,-17.247 64.82,-18.541 SW2.1@65.289,-18.541 ; SW2.1@66.069,-18.281 66.672,-17.678 72.216,-17.678 SW2.1@72.819,-18.281
  Top Layer w0.254: P5.2@7.62,-13.018 v1(8.89,-14.287)
  Bottom Layer w0.152: v1(8.89,-14.287) 8.331,-14.846 8.331,-16.388 9.291,-17.348 12.19,-17.348 13.409,-16.129 36.304,-16.129 36.99,-15.443 v1(37.719,-15.443) ; v1(13.487,8.433) 13.818,8.103 13.818,7.806 14.122,7.501 14.122,7.499 15.928,5.693 19.663,5.693 20.302,5.055 v1(20.625,5.055)
CTS: SB9.1 U3.38 | length 11.2
  Top Layer w0.152: SB9.1@31.233,5.662 31.792,5.662 36.77,0.684 38.456,0.684 39.041,1.27 U3.38@40.101,1.27
DEC1: C8.1 U1.39 | length 1.3
  Top Layer w0.203: U1.39@11.706,-2.147 11.706,-3.055 C8.1@12.016,-3.365
DEC2: C10.1 U1.29 | length 2.4
  Top Layer w0.152: C10.1@8.433,2.893 8.433,2.719 9.699,1.453 U1.29@10.106,1.453
DFSD_N: R11.1 U3.80 | length 23.9
  Top Layer w0.35: v1@52.883,-2.914 cw(c53.322,-3.353) 53.322,-2.733 ; 53.365,-2.733 U3.80@55.251,-2.733 ; v1(58.242,-9.881) 62.031,-9.881 ccw(c62.031,-7.341) 63.827,-9.137 66.394,-6.57 ccw(c66.022,-6.198) 66.548,-6.198 ccw(c65.935,-6.198) 66.368,-5.764 R11.1@66.063,-5.459
  Bottom Layer w0.35: v1(52.883,-2.912) 52.672,-3.122 ccw(c54.249,-4.699) 52.019,-4.699 ccw(c54.472,-4.699) 52.738,-6.433 55.441,-9.137 ccw(c57.237,-7.341) 57.237,-9.881 v1(58.242,-9.881)
DFSD_P: R10.1 U3.81 | length 23.8
  Top Layer w0.35: v1@52.883,-2.048 ccw(c53.322,-1.609) 53.322,-2.23 ; 53.34,-2.23 U3.81@55.251,-2.23 ; v1(58.725,-4.089) ccw(c58.909,-3.905) 58.909,-4.166 62.03,-4.166 ccw(c62.03,-3.658) 62.538,-3.658 62.538,-2.137 ; 62.538,-2.159 cw(c63.046,-2.159) 63.046,-1.651 ccw(c63.046,-1.143) 63.554,-1.143 63.554,0.377 ; 63.554,0.354 cw(c64.062,0.354) 64.57,0.354 64.57,-1.724 cw(c64.062,-1.724) 64.062,-2.232 ccw(c64.062,-2.74) 63.703,-3.099 R10.1@64.035,-3.431
  Bottom Layer w0.35: v1@52.883,-2.048 54.793,-2.048 cw(c54.793,-4.588) 56.589,-2.792 57.294,-3.497 ccw(c58.725,-2.066) v1(58.725,-4.089)
  other v1: 52.883,-2.051
DHSD_N: D2.2 J1.2 R11.2 U3.77 | length 25.4
  Top Layer w0.203: U3.77@54.656,-4.23 U3.77@55.251,-4.23 ; U3.77@54.656,-4.221 ccw(c54.656,-4.827) 54.227,-5.256 56.1,-7.129 ccw(c57.023,-6.206) 57.023,-7.511 61.514,-7.511 ccw(c61.514,-5.763) 62.75,-6.999 ; 62.747,-6.996 68.96,-0.783 cw(c69.438,-1.261) 69.438,-0.585 70.432,-0.585 cw(c70.432,-1.714) 71.23,-0.916 71.74,-1.425 D2.2@71.74,-1.431 ; D2.2@71.75,-1.408 72.209,-0.949 cw(c72.568,-1.308) 72.568,-0.8 J1.2@73.4,-0.8
  Top Layer w0.35: D2.2@71.74,-1.431 cw(c71.773,-1.431) D2.2@71.749,-1.408
DHSD_P: D2.3 J1.3 R10.2 U3.76 | length 25.4
  Top Layer w0.203: U3.76@55.251,-4.73 55.813,-4.73 cw(c55.813,-5.708) 56.505,-5.017 ccw(c56.75,-4.771) 56.75,-5.118 57.353,-5.118 ; 57.015,-7.153 61.524,-7.153 ccw(c61.524,-5.794) 62.485,-6.755 ; 57.048,-7.15 cw(c57.048,-6.642) 57.048,-6.134 57.348,-6.134 ; 57.358,-6.134 ccw(c57.358,-5.626) 57.358,-5.118 ; 62.475,-6.765 68.707,-0.533 cw(c69.444,-1.27) 69.444,-0.228 70.433,-0.228 ccw(c70.433,0.901) 71.23,0.103 D2.3@71.74,0.612 ; D2.3@71.74,0.619 72.209,0.15 ; 72.209,0.149 ccw(c72.568,0.508) 72.568,0 J1.3@73.4,0
  Top Layer w0.35: D2.3@71.74,0.612 D2.3@71.74,0.619
ENSPI: U3.21 U3.99 | length 15
  Top Layer w0.152: U3.21@43.676,8.845 43.676,6.896 44.755,5.817 47.473,5.817 49.2,7.544 51.843,7.544 52.617,6.77 U3.99@55.251,6.77
GND: C1.2 C2.2 C3.2 C4.2 C6.2 C7.2 C8.2 C9.2 C10.2 C11.2 C12.1 C13.2 C14.2 C15.2 C16.1 C17.1 C18.1 C19.1 C21.1 C22.1 C23.1 C24.2 C25.2 C26.2 C27.1 C28.1 C29.1 C30.1 C31.1 C32.1 C33.1 C34.1 C35.1 C36.1 C37.1 C38.1 C39.1 C40.1 C41.1 C42.1 C43.1 D2.1 J1.5 J2.3 LD1.1 LD2.1 P1.4 P3.9 P4.9 P5.9 P6.9 R1.1 R2.1 R9.1 R12.1 R18.1 R19.2 SB17.2 SB18.2 SW1.2 SW2.2 SW3.2 SW4.3 U1.13 U1.33 U1.34 U1.49 U2.3 U3.3 U3.35 U3.46 U3.61 U3.72 U3.82 U3.89 U4.8 X1.2 X1.4 X3.2 X3.4 | length 37.6
  Top Layer w0.229: C1.2@9.4,-7.099 10.004,-6.495 X1.4@10.004,-6.212 9.525,-5.733 v1(9.525,-4.862) ; v1@9.5,-4.862 v1(9.525,-4.862) ; C9.2@9.83,-4.015 9.83,-4.608 9.576,-4.862 v1(9.525,-4.862) ; U1.34@10.106,-0.547 U1.49@11.706,-0.547 ; U1.33@10.106,-0.147 U1.49@12.106,-0.147 ; U1.49@13.106,0.853 U1.49@15.306,3.053 ; 16.192,-2.766 C7.2@17.145,-3.657 ; C12.1@18.974,-2.474 C12.1@18.974,-2.296 ; v1@72.212,1.473 72.736,1.473 72.863,1.6 J1.5@73.4,1.6
  Top Layer w0.254: X1.2@12.196,-5.717 C2.2@12.774,-5.139 ; 16.212,4.198 C11.2@17.196,4.198 17.196,5.309 ; R19.2@38.506,-5.952 38.803,-5.952 v1(39.345,-5.41) 38.93,-4.996 C32.1@38.506,-4.996 ; v1(38.862,-2.819) 38.951,-2.73 U3.46@40.101,-2.73 ; U3.61@46.676,-6.305 46.676,-7.385 46.685,-7.395 46.685,-7.518 46.761,-7.595 46.99,-7.595 C37.1@47.828,-8.433 ; C26.2@51.412,-7.851 52.176,-7.087 U3.72@52.176,-6.305 ; C25.2@51.968,-9.558 X3.4@53.086,-9.558 ; U3.3@52.688,8.857 C33.1@52.688,10.312 ; X3.4@53.086,-9.168 53.138,-9.168 53.138,-7.976 v1(53.365,-7.976) ; U3.82@55.251,-1.73 56.688,-1.73 C30.1@56.896,-1.938 ; U3.89@55.251,1.77 56.262,1.77 56.853,2.361 C38.1@56.853,2.743 ; R12.1@58.141,-1.938 58.141,-1.676 58.699,-1.118 v1@58.979,-1.118 ; 67.018,1.778 68.791,1.778 C23.1@68.791,1.676
  Top Layer w0.381: C7.2@17.145,-3.657 17.598,-3.657 C12.1@18.948,-2.307
  other v1: 21.488,-19.355 34.265,-19.253 38.202,-19.228 16.561,-19.202 19.152,-19.152 52.146,-19.152 75.717,-18.745 69.32,-18.54 79.223,-18.466 63.46,-18.37 50.724,-18.161 57.27,-18.05 36.805,-18.009 16.51,-17.297 45.822,-17.297 23.56,-17.16 69.901,-16.637 74.905,-16.281 49.352,-16.129 72.746,-15.697 42.951,-15.596 64.948,-15.367 78.257,-15.037 19.355,-14.656 56.718,-14.376 16.586,-14.351 59.157,-14.326 34.29,-14.275 64.059,-14.097 43.637,-13.792 74.93,-13.792 79.324,-13.741 40.081,-13.386 8.865,-13.233 20.269,-13.183 52.146,-13.132 11.43,-13.03 59.69,-12.268 18.974,-11.862 48.387,-11.862 24.028,-11.659 16.51,-11.608 51.867,-11.532 74.27,-11.328 78.283,-11.303 57.15,-11.278 39.116,-11.049 54.28,-10.897 49.479,-10.77 62.916,-10.566 43.434,-10.414 7.239,-10.389 12.395,-10.338 45.796,-10.287 46.634,-10.287 71.704,-10.287 32.893,-10.109 51.13,-9.576 39.548,-9.347 66.904,-9.093 54.102,-9.068 65.049,-9.017 70.968,-8.966 32.41,-8.941 23.19,-8.915 26.137,-8.738 20.904,-8.458 16.231,-8.407 73.66,-8.331 48.565,-8.204 13.259,-7.91 43.18,-7.823 7.849,-7.783 50.698,-7.798 46.939,-7.544 39.548,-7.417 68.529,-7.036 18.847,-6.833 34.29,-6.833 13.005,-6.716 71.907,-6.68 17.374,-6.477 29.972,-6.452 7.036,-5.522 37.49,-5.486 46.711,-5.004 51.283,-5.004 13.284,-4.709 17.145,-4.557 20.93,-4.42 23.19,-4.191 35.204,-4.14 26.162,-4.115 37.414,-3.861 41.808,-3.708 30.886,-3.454 61.62,-3.378 47.498,-3.353 72.238,-2.642 70.383,-2.553 16.154,-2.423 33.223,-2.184 59.893,-1.88 57.531,-1.803 35.789,-1.219 59.106,-1.092 6.629,-1.026 62.586,-0.635 51.689,-0.584 65.532,-0.508 44.374,-0.229 57.658,0 59.157,0.051 31.81,0.87 23.774,1.524 60.528,1.575 67.64,1.689 58.522,1.702 72.263,1.753 53.772,1.829 41.478,2.007 70.79,2.464 43.942,2.515 47.93,2.642 67.437,2.718 36.322,2.794 38.837,2.87 37.287,2.896 63.271,2.946 52.68,3.073 56.82,3.505 71.374,3.734 49.962,3.861 15.951,3.901 78.334,4.343 7.518,4.714 8.306,4.714 23.35,4.73 16.485,4.75 36.17,4.978 61.697,4.978 47.346,5.004 71.679,5.74 37.668,6.147 56.617,6.147 76.048,6.426 41.783,6.452 26.64,6.53 49.86,7.01 11.43,7.137 35.357,7.366 53.315,7.442 59.817,7.569 78.613,7.874 40.132,8.23 70.714,8.306 73,8.331 54.915,8.636 65.481,9.093 39.243,9.398 76.2,9.779 10.668,9.982 50.902,10.287 7.239,10.363 73.812,10.414 78.943,10.77 56.693,10.82 64.135,10.897 52.73,11.125 42.037,11.201 40.691,11.328 50.368,11.328 38.76,11.405 21.158,11.43 42.59,12.79 40,12.88 47.041,12.954 8.941,13.132 51.269,14.055 56.82,14.326 41.04,14.65 74.905,14.859 19.888,15.088 26.67,15.164 78.969,15.215 8.915,15.342 62.84,15.621 59.614,15.697 71.196,15.926 37.58,16.03 55.88,17.247 21.412,17.399 38.76,17.43 63.424,17.958 48.39,18.06 44.919,18.094 43.369,18.246 71.196,18.644 73.914,18.872 79.019,19.101 8.865,19.177 19.177,19.177 26.695,19.177
  other v2: 11.306,-0.947 12.506,-0.947 13.706,-0.947 14.906,-0.947 11.306,0.253 12.506,0.253 13.706,0.253 14.906,0.253 11.306,1.453 12.506,1.453 13.706,1.453 14.906,1.453 11.306,2.653 12.506,2.653 13.706,2.653 14.906,2.653
LED0: P5.3 SB6.1 U1.26 | length 85.5
  Top Layer w0.152: U1.26@10.106,2.653 9.792,2.653 9.528,2.917 9.528,3.302 10.236,4.011 10.236,7.213 11.99,8.966 v1(12.929,8.966) ; v1(21.184,5.588) 21.515,5.588 22.022,5.081 22.022,4.174 22.022,0.213 23.734,-1.499 26.951,-1.499 33.428,-7.976 36.804,-7.976 37.795,-8.967 37.795,-10.055 37.795,-14.503 v1@38.024,-14.732
  Top Layer w0.254: v1(8.89,-16.192) P5.3@10.16,-17.462 ; v1(38.136,-14.783) 38.075,-14.783 39.319,-16.027 SB6.1@40.564,-16.027
  Bottom Layer w0.152: v1(8.89,-16.192) 9.741,-17.043 12.064,-17.043 13.283,-15.824 36.178,-15.824 37.27,-14.732 38.085,-14.732 v1(38.136,-14.783) ; v1(12.929,8.966) 13.716,8.966 14.122,8.56 14.122,7.932 16.056,5.998 19.789,5.998 20.199,5.588 v1(21.184,5.588)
